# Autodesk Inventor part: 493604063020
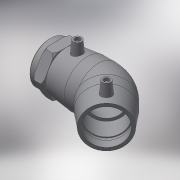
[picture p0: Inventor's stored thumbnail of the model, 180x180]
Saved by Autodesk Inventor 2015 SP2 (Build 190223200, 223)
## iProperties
Created: 2017-06
Part Number: 493604063020
Material: Generic
Description: PLASSON 45° ELBOW TRANSITION FEMALE 63-2"
Document SubType Name: Modeling
Designer: KIM
Mass: 432.728 g
Surface Area: 873.139 cm^2
Volume: 432.728 cm^3
Density: 1 g/cm^3
Appearance: Default
Author: KIM
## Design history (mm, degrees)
derived "493604.ipt"
feature "Solid1::493604.ipt"
tag "TaggingFeature1"
body "Solid1"
other parameters: "d2" = 82, "d4" = 37, "d5" = 73.8, "d8" = 168 deg, "d10" = 22.8, "d11" = 7.6, "d29" = 59, "d30" = 15, "d31" = 51.8, "d34" = 5 deg, "d41" = 4, "d42" = 14, "d43" = 0, "d49" = 63, "d50" = 53.55, "d51" = 22.8, "d52" = 57, "d54" = 135 deg, "d86" = 36.9, "d87" = 135 deg, "d88" = 148, "d90" = 57, "d91" = 0, "d92" = 57, "d93" = 0, "d101" = 3, "d102" = 0, "d107" = 0.1, "d108" = 48, "d112" = 73.8, "d113" = 56.656, "d114" = 27, "d128" = 18, "d129" = 0, "d132" = 3.15, "d133" = 45 deg, "d134" = 45 deg, "d136" = 1.89, "d_" = 63, "L_" = 178, "L_1" = 57, "D_" = 48, "A_" = 59, "d_2" = 12, "Rp_" = 56.656, "D_1" = 82
